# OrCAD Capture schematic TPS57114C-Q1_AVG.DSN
size E; title: TPS57114C-Q1 Automotive 2.95-V to 6-V,; rev: 1.0; note: Datasheet: SLVSDQ7A         EVM: SLVU963; note: Synchronous Step Down Converter; note: 4-A 2-MHz Synchronous Buck Converter
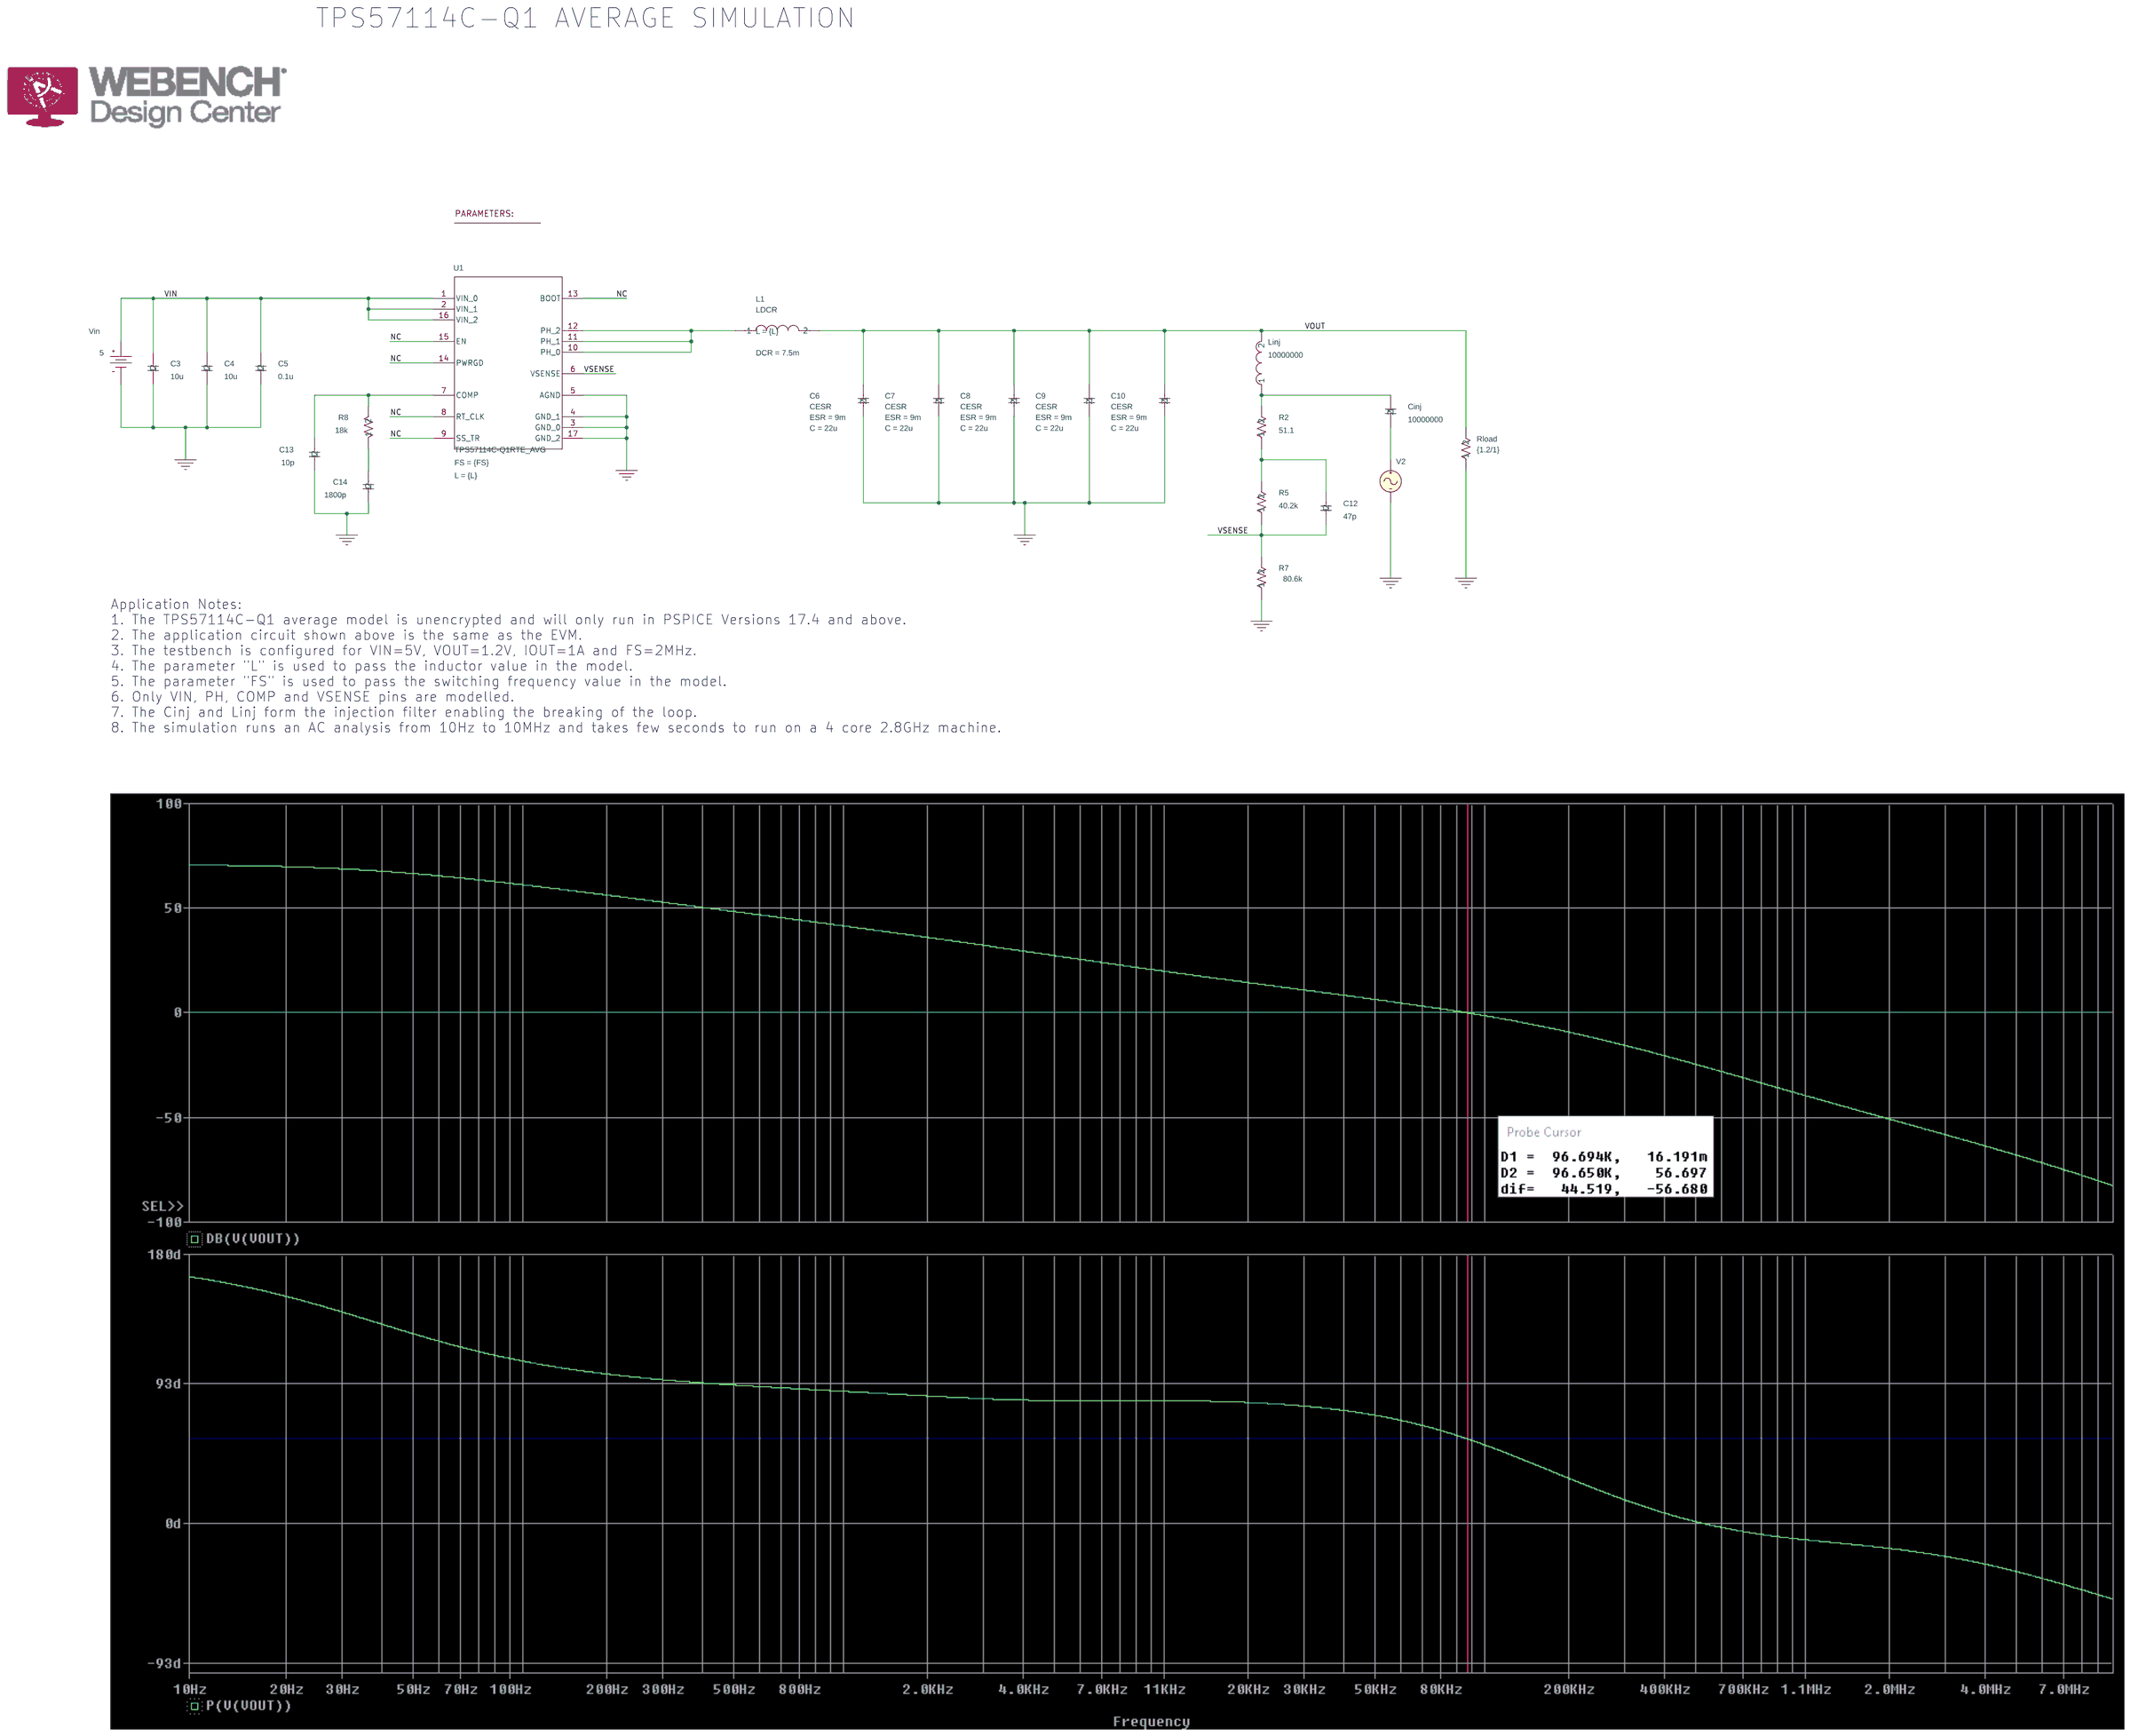
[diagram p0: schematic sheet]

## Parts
1  PARAM
C3  10u  [RAD/CK05]
C4  10u  [RAD/CK05]
C5  0.1u  [RAD/CK05]
C6  CESR
C7  CESR
C8  CESR
C9  CESR
C10  CESR
C12  47p  [RAD/CK05]
C13  10p  [RAD/CK05]
C14  1800p  [RAD/CK05]
Cinj  10000000  [RAD/CK05]
L1  LDCR
Linj  10000000  [DISC/.350x.175/LS.200x.100/.034]
R2  51.1  [AX/RC05]
R5  40.2k  [AX/RC05]
R7  80.6k  [AX/RC05]
R8  18k  [AX/RC05]
Rload  {1.2/1}  [AX/RC05]
U1  TPS57114C-Q1RTE_AVG  [RTE0016F]
V2  VAC
Vin  VDC

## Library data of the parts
1 = PARAM: FS: 2e6; L: 0.75E-6
C3 = c_1
C4 = c_5
C5 = c_6
C6 = CESR: C: 22u; ESR: 9m; PSpiceTemplate: X^@REFDES %1 %2 @MODEL PARAMS: ?C|C=@C||C=10U| ?ESR|ESR=@ESR||ESR=2M|  ?X|X=@X||X=1|; X: 1
C7 = CESR_4: C: 22u; ESR: 9m; PSpiceTemplate: X^@REFDES %1 %2 @MODEL PARAMS: ?C|C=@C||C=10U| ?ESR|ESR=@ESR||ESR=2M|  ?X|X=@X||X=1|; X: 1
C8 = CESR_3: C: 22u; ESR: 9m; PSpiceTemplate: X^@REFDES %1 %2 @MODEL PARAMS: ?C|C=@C||C=10U| ?ESR|ESR=@ESR||ESR=2M|  ?X|X=@X||X=1|; X: 1
C9 = CESR_2: C: 22u; ESR: 9m; PSpiceTemplate: X^@REFDES %1 %2 @MODEL PARAMS: ?C|C=@C||C=10U| ?ESR|ESR=@ESR||ESR=2M|  ?X|X=@X||X=1|; X: 1
C10 = CESR_1: C: 22u; ESR: 9m; PSpiceTemplate: X^@REFDES %1 %2 @MODEL PARAMS: ?C|C=@C||C=10U| ?ESR|ESR=@ESR||ESR=2M|  ?X|X=@X||X=1|; X: 1
C12 = c_3
C13 = c
C14 = c_2
Cinj = c_4
L1 = LDCR: DCR: 7.5m; L: {L}
Linj = l
R2 = r_4
R5 = r
R7 = r_2
R8 = r_1
Rload = r_3
U1 = TPS57114C-Q1RTE_AVG: FS: {FS}; L: {L}
V2 = VAC
Vin = VDC: DC: 5

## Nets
VIN: C3.2 C4.2 C5.2 U1.1(VIN_0) U1.2(VIN_1) U1.16(VIN_2) Vin.0(+)
0: C3.1 C4.1 C5.1 C6.2 C7.2 C8.2 C9.2 C10.2 C13.1 C14.1 R7.1 Rload.1 U1.3(GND_0) U1.4(GND_1) U1.5(AGND) U1.17(GND_2) V2.2(-) Vin.1(-)
NC: U1.8(RT_CLK) U1.9(SS_TR) U1.13(BOOT) U1.14(PWRGD) U1.15(EN)
VOUT: C6.1 C7.1 C8.1 C9.1 C10.1 L1.2 Linj.2 Rload.2
VSENSE: C12.1 R5.1 R7.2 U1.6(VSENSE)
N16819202: L1.1 U1.10(PH_0) U1.11(PH_1) U1.12(PH_2)
N16819283: C12.2 R2.1 R5.2
N16819387: C13.2 R8.2 U1.7(COMP)
N16819392: C14.2 R8.1
N16819512: Cinj.1 Linj.1 R2.2
N16819544: Cinj.2 V2.1(+)

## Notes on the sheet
- TPS57114C-Q1 AVERAGE SIMULATION
- Application Notes:
  1. The TPS57114C-Q1 average model is unencrypted and will only run in PSPICE Versions 17.4 and above.
  2. The application circuit shown above is the same as the EVM.
  3. The testbench is configured for VIN=5V, VOUT=1.2V, IOUT=1A and FS=2MHz.
  4. The parameter "L" is used to pass the inductor value in the model.
  5. The parameter "FS" is used to pass the switching frequency value in the model.
  6. Only VIN, PH, COMP and VSENSE pins are modelled.
  7. The Cinj and Linj form the injection filter enabling the breaking of the loop.
  8. The simulation runs an AC analysis from 10Hz to 10MHz and takes few seconds to run on a 4 core 2.8GHz machine.
